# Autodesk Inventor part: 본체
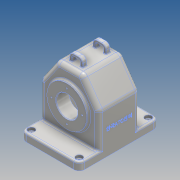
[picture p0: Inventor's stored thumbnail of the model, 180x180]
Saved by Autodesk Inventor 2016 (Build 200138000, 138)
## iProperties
Created: 2016-12
Part Number: 본체
Material: 알루미늄 6061
Document SubType Name: Modeling
Designer: Administrator
Density: 2.7 g/cm^3
Appearance: 알루미늄 - 평지
Mass: 1062.86 g
Surface Area: 1137.38 cm^2
Volume: 393.653 cm^3
Author: Administrator
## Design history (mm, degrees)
sketch "스케치1"
  geometry: L1 (45, -75)-(-45, -75); L2 (-55, -65)-(-55, 65); L3 (-45, 75)-(45, 75); L4 (55, 65)-(55, -65); L5 (55, -75)-(-55, 75); L6 (-55, -75)-(55, 75); A1 r 10 centre (-45, 65) between (-45, 75) and (-55, 65); A2 r 10 centre (45, 65) between (55, 65) and (45, 75); A3 r 10 centre (45, -65) between (45, -75) and (55, -65); A4 r 10 centre (-45, -65) between (-55, -65) and (-45, -75); 1 further point
  constraints: 12 end point, 8 point on circle, 8 point on line, 8 tangent, 4 centre point, 3 equal radius, 2 midpoint, 2 parallel, 1 horizontal, 1 perpendicular
  dimensions: "d0" = 110 distance of L5.end L6.end; "d1" = 150 distance of L6.start L5.end; "d2" = 10 radius of A1
extrude "돌출1" new body sketch "스케치1" distance "d3" = 15; taper "d4" = 0 deg
node "작업 평면1"
sketch "스케치2"
  geometry: L1 (55, 0)-(55, 15) reference; L2 (-55, 0)-(-55, 15) reference; L3 (45, 15)-(-45, 15) reference; L4 (55, 15)-(55, 80); L5 (55, 80)-(23.491, 125); L6 (23.491, 125)-(-23.491, 125); L7 (-23.491, 125)-(-55, 80); L8 (-55, 80)-(-55, 15); L9 (-45, 0)-(45, 0) reference; L10 (0, 125)-(0, 0)
  constraints: 12 end point, 2 perpendicular, 1 midpoint, 1 parallel, 1 vertical, 1 other
  dimensions: "d6" = 80 distance from line of L9 L4.end; "d7" = 125 distance between parallel lines of L9 L6; "d8" = 35 deg angle of L8 L7
extrude "돌출2" join sketch "스케치2" distance "d10" = 77; taper "d11" = 0 deg
node "작업 평면2"
sketch "스케치6"
  geometry: L1 (-55, 15)-(-55, 80) reference; L2 (-55, 80)-(-23.491, 125) reference; L3 (-23.491, 125)-(23.491, 125) reference; L4 (23.491, 125)-(55, 80) reference; L5 (55, 80)-(55, 15) reference; L6 (55, 0)-(55, 15) reference; L7 (-45, 0)-(45, 0) reference; L8 (-55, 0)-(-45, 0) reference; L9 (-55, 0)-(-55, 15) reference; L10 (45, 0)-(55, 0) reference; L11 (20.888, 120)-(-20.888, 120); L12 (-20.888, 120)-(-50, 78.424); L13 (-50, 78.424)-(-50, 15); L14 (-50, 15)-(-50, 0); L15 (50, 0)-(50, 15); L16 (50, 15)-(50, 78.424); L17 (50, 78.424)-(20.888, 120); L18 (50, 0)-(-50, 0); 1 further point
  constraints: 16 end point, 2 midpoint, 1 collinear, 3 other
  dimensions: "d30" = 5 distance between parallel lines of L3 L11
extrude "돌출3" cut sketch "스케치6" distance "d31" = 67; taper "d32" = 0 deg
sketch "스케치4"
  geometry: L1 (-43.5, 65)-(48.5, 65); L2 (-38.5, 102.5)-(-43.5, 102.5); L3 (-43.5, 102.5)-(-43.5, 65); L4 (38.5, 80)-(38.5, 125) reference; L5 (38.5, 96)-(48.5, 96); L6 (48.5, 96)-(48.5, 65); L7 (-38.5, 102.5)-(-38.5, 65); L8 (38.5, 96)-(38.5, 65); L9 (38.5, 15)-(38.5, 80) reference; L10 (-38.5, 80)-(-38.5, 125) reference; 1 further point
  constraints: 14 end point, 4 point on line, 3 horizontal, 3 perpendicular, 1 vertical alignment
  dimensions: "d13" = 65 vertical distance of L1.start point (0, 0); "d14" = 75 diameter of L2 L1; "d15" = 62 diameter of L5 L1; "d16" = 5 distance of L2.start L2.end; "d17" = 87 distance from line of L10 L5.end
revolve "회전1" sketch "스케치4" stored, may be unused: angle "d18" = 90 deg
sketch "스케치7"
  geometry: L1 (-33.5, 120)-(-33.5, 78.424) reference; L2 (-33.5, 78.424)-(-33.5, 0) reference; L3 (-33.5, 65)-(33.5, 65); L4 (33.5, 0)-(33.5, 78.424) reference; L5 (-19.5, 92)-(-19.5, 65); L6 (-43.5, 27.5)-(-43.5, 102.5) reference; L7 (-19.5, 92)-(-33.5, 106); 1 further point
  constraints: 6 end point, 4 point on line, 2 perpendicular
  dimensions: "d33" = 54 diameter of L5.start L3; "d34" = 130 diameter of point (0, 0) L3; "d36" = 24 distance between parallel lines of L6 L5; "d37" = 45 deg angle of L5 L7
revolve "회전3" sketch "스케치7" stored, may be unused: angle "d38" = 90 deg
hole "구멍1" diameter "d41" = 40; stored, may be unused: countersink angle "d45" = 90 deg, drill point angle "d47" = 118 deg; dims "d39" = 10, "d40" = 10, "d42" = 6, "d43" = 4, "d44" = 2, "d46" = 8
chamfer "모따기1" distance "d48" = 1; stored, may be unused: second distance "d49" = 2, angle "d50" = 45 deg
fillet "모깎기1" dims "d51" = 3
fillet "모깎기2" dims "d52" = 3
node "작업 평면3"
sketch "스케치8"
  geometry: L1 (12.5, 125)-(12.5, 132); L2 (4.5, 140)-(-4.5, 140); L3 (-12.5, 132)-(-12.5, 125); L4 (23.491, 125)-(-23.491, 125) reference; L5 (23.491, 125)-(-23.491, 125) reference; L6 (-45, 0)-(45, 0) reference; L7 (0, 125)-(0, 140); L8 (-7.5, 125)-(-7.5, 132); L9 (-4.5, 135)-(4.5, 135); L10 (7.5, 132)-(7.5, 125); L11 (7.5, 125)-(12.5, 125); L12 (-7.5, 125)-(-12.5, 125); L13 (47, 0)-(47, 77.478) reference; A1 r 8 centre (4.5, 132) between (12.5, 132) and (4.5, 140); A2 r 8 centre (-4.5, 132) between (-4.5, 140) and (-12.5, 132); A3 r 3 centre (-4.5, 132) between (-4.5, 135) and (-7.5, 132); A4 r 3 centre (4.5, 132) between (7.5, 132) and (4.5, 135); 3 further points
  constraints: 18 end point, 8 point on circle, 8 point on line, 5 perpendicular, 4 centre point, 4 tangent, 2 midpoint, 2 vertical, 1 collinear, 1 equal radius, 5 other
  dimensions: "d54" = 25 distance of point (12.5, 140) point (-12.5, 140); "d55" = 140 distance between parallel lines of L6 L2; "d56" = 8 radius of A1; "d57" = 5 distance between parallel lines of L2 L9
extrude "돌출4" join sketch "스케치8" distance "d60" = 8; taper "d61" = 0 deg
fillet "모깎기3" dims "d62" = 1
fillet "모깎기4" dims "d63" = 1
sketch "스케치9"
  geometry: C1 r 37.5 at (0, 0) reference; C2 r 21 at (0, 0) reference; A1 r 29 centre (0, 0) between (0, 29) and (0, -29); 3 further points
  constraints: 4 point on circle, 2 horizontal alignment, 2 vertical alignment, 1 centre point, 1 coincident
  dimensions: "d64" = 58 diameter of A1
hole "구멍2" sketch "스케치9" at (0, 29), (0, -29), (-29, 0), (29, 0) diameter "d65" = 2.459; stored, may be unused: countersink angle "d69" = 90 deg, drill point angle "d71" = 118 deg; dims "d66" = 6, "d67" = 4, "d68" = 2, "d70" = 8.8
sketch "스케치10"
  geometry: C1 r 31 at (0, 0) reference; C2 r 21 at (0, 0) reference; A1 r 26 centre (0, 0) between (-26, 0) and (26, 0); 3 further points
  constraints: 4 point on circle, 2 horizontal alignment, 2 vertical alignment, 1 centre point, 1 coincident
  dimensions: "d72" = 52 diameter of A1
hole "구멍3" sketch "스케치10" at (-26, 0), (26, 0), (0, -26), (0, 26) diameter "d73" = 2.459; stored, may be unused: countersink angle "d77" = 90 deg, drill point angle "d79" = 118 deg; dims "d74" = 6, "d75" = 4, "d76" = 2, "d78" = 8
sketch "스케치11"
  geometry: A1 r 10 centre (-45, -65) between (-55, -65) and (-45, -75) reference; A2 r 10 centre (45, -65) between (45, -75) and (55, -65) reference; A3 r 10 centre (-45, 65) between (-45, 75) and (-55, 65) reference; A4 r 10 centre (45, 65) between (55, 65) and (45, 75) reference; 5 further points
  constraints: 4 coincident
hole "구멍4" sketch "스케치11" at (-45, -65), (45, -65), (-45, 65), (45, 65) diameter "d80" = 5; stored, may be unused: countersink angle "d84" = 90 deg, drill point angle "d86" = 118 deg; dims "d81" = 6, "d82" = 12, "d83" = 5, "d85" = 8
fillet "모깎기5" dims "d87" = 10
fillet "모깎기6" dims "d88" = 8
fillet "모깎기7" dims "d89" = 3
node "작업 평면4"
sketch "스케치12" dims "d0" = 110, "d1" = 150, "d2" = 10
  geometry: L1 (-38.5, 76.847)-(-38.5, 18) reference; 3 further points
  constraints: 1 coincident, 1 other
  dimensions: "d91" = 45 distance of point (0, 0) point (0, 45); "d92" = 38.5 horizontal distance of L1.end point (0, 45)
feature "엠보싱1" sketch "스케치12" dims "d0" = 110, "d1" = 150, "d2" = 10, "d93" = 0.5, "d94" = 0
node "솔리드1"
mirror "대칭1"
other parameters: "d5" = -38.5, "d9" = 77, "d29" = -5, "d53" = -26
